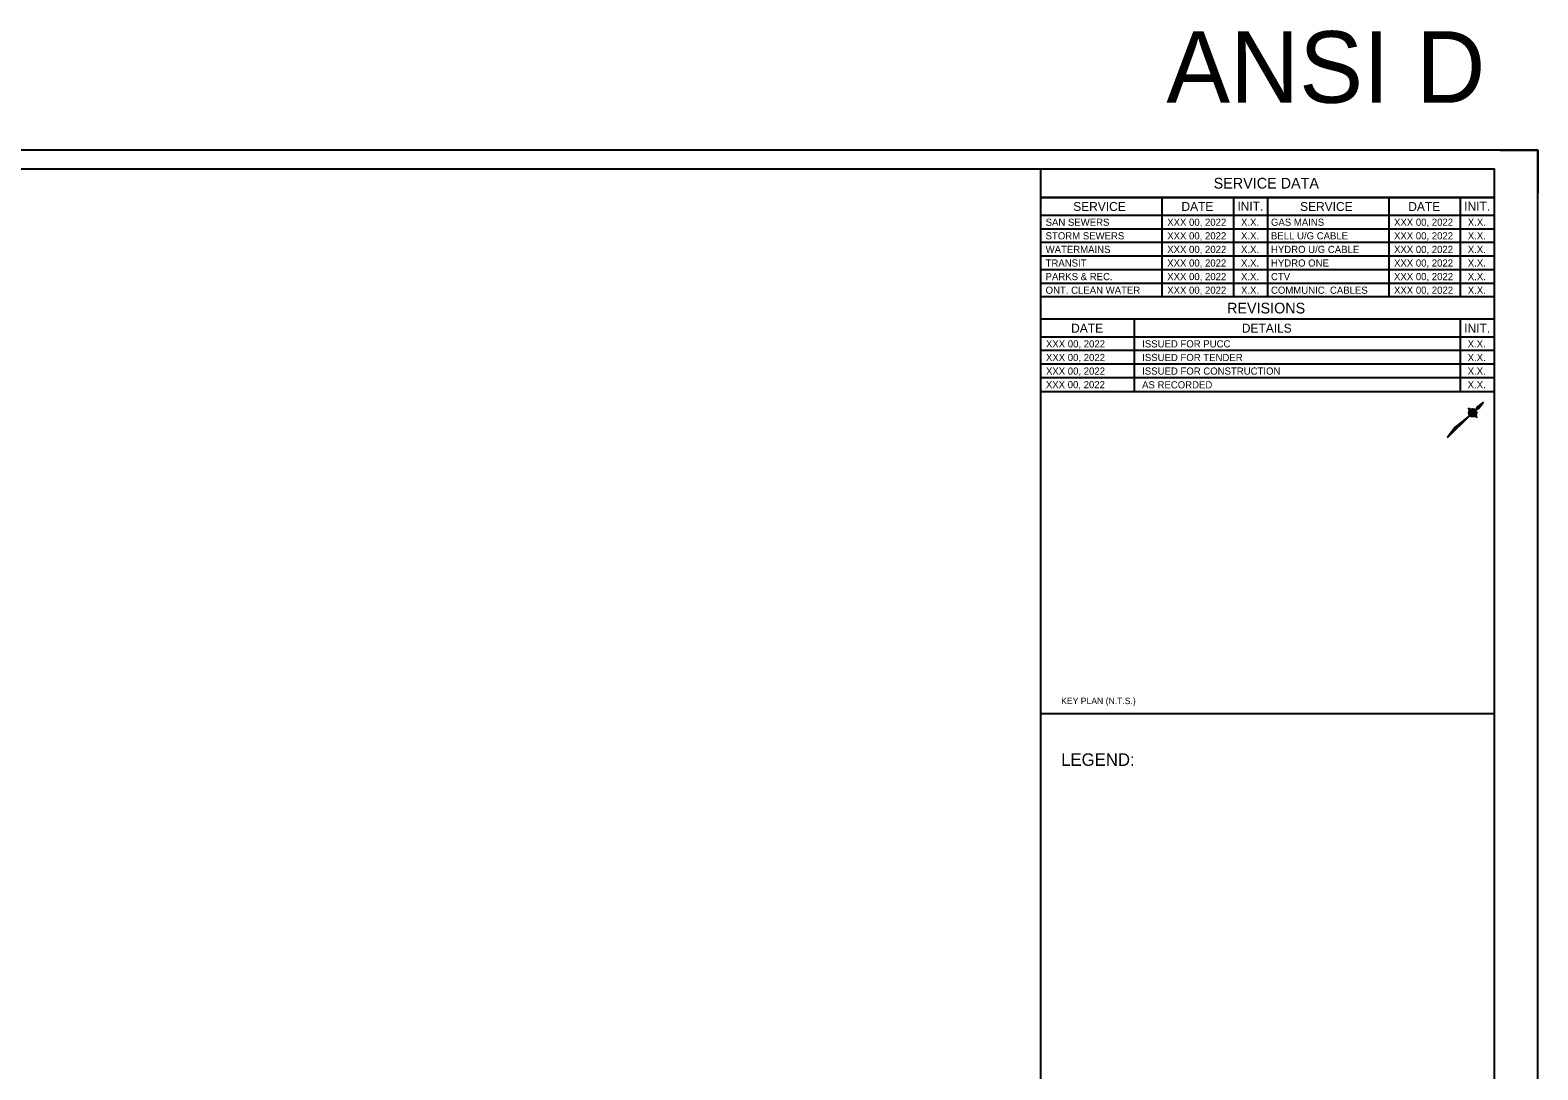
# Model space of a CAD drawing. Extents: x 613360 to 613780, y 4825621 to 4825911.
# Drawn here: x 613569.5 to 613780.3, y 4825766.2 to 4825911.5 of the extents above; entities that cross this region are included whole.
import ezdxf

# ---------------------------------------------------------------- set-up
doc = ezdxf.new("R2010")
doc.units = 0
for name, color, linetype in [('G-ANNO-KEYP', 7, 'Continuous'), ('G-ANNO-LEGN', 7, 'Continuous'), ('G-ANNO-NPLT', 7, 'Continuous'), ('G-ANNO-TTLB-TEXT', 7, 'Continuous'), ('G-TTLB-OTLN', 7, 'Continuous'), ('G-TTLB-OTLN-PB', 7, 'Continuous')]:
    doc.layers.add(name, color=color, linetype=linetype)

msp = doc.modelspace()

# ---------------------------------------------------------------- linework, layer by layer
at = {"layer": 'G-ANNO-KEYP'}
for p, q in [((613770.76, 4825857.62), (613767.64, 4825854.56)), ((613767.74, 4825854.69), (613770.74, 4825857.6)), ((613770.76, 4825857.62), (613768.73, 4825855.97)), ((613770.77, 4825858.38), (613770.51, 4825858.64)), ((613770.56, 4825858.46), (613770.71, 4825858.31)), ((613770.68, 4825858.07), (613770.78, 4825858.17)), ((613770.68, 4825858.05), (613770.76, 4825858.13)), ((613770.68, 4825858.03), (613770.76, 4825858.11)), ((613770.68, 4825858.01), (613770.75, 4825858.08)), ((613770.68, 4825857.99), (613770.74, 4825858.06)), ((613770.68, 4825857.97), (613770.74, 4825858.04)), ((613770.68, 4825857.96), (613770.74, 4825858.02)), ((613770.68, 4825857.94), (613770.74, 4825858)), ((613770.68, 4825857.92), (613770.74, 4825857.98)), ((613770.68, 4825857.91), (613770.74, 4825857.96)), ((613770.69, 4825858.59), (613770.84, 4825858.44)), ((613770.69, 4825858.12), (613770.85, 4825858.28)), ((613770.69, 4825858.1), (613770.8, 4825858.2)), ((613770.69, 4825857.89), (613770.74, 4825857.94)), ((613770.69, 4825857.87), (613770.75, 4825857.93)), ((613770.7, 4825858.15), (613771.01, 4825858.44)), ((613770.7, 4825857.86), (613770.75, 4825857.91)), ((613770.7, 4825857.85), (613770.75, 4825857.9)), ((613770.71, 4825858.18), (613770.97, 4825858.43)), ((613770.71, 4825857.83), (613770.76, 4825857.88)), ((613770.71, 4825857.82), (613770.76, 4825857.87)), ((613770.72, 4825857.8), (613770.77, 4825857.85)), ((613770.72, 4825857.79), (613770.77, 4825857.84)), ((613770.73, 4825858.21), (613770.94, 4825858.42)), ((613770.73, 4825857.78), (613770.78, 4825857.82)), ((613770.74, 4825857.77), (613770.78, 4825857.81)), ((613770.74, 4825857.75), (613770.79, 4825857.8)), ((613770.75, 4825857.74), (613770.8, 4825857.79)), ((613770.76, 4825858.26), (613770.89, 4825858.39)), ((613770.76, 4825857.73), (613770.8, 4825857.78)), ((613770.77, 4825857.72), (613770.81, 4825857.76)), ((613770.77, 4825857.71), (613770.82, 4825857.75)), ((613770.78, 4825857.7), (613770.83, 4825857.74)), ((613770.79, 4825857.69), (613770.84, 4825857.73)), ((613770.8, 4825857.68), (613770.85, 4825857.72)), ((613770.81, 4825857.67), (613770.86, 4825857.71)), ((613770.82, 4825857.66), (613770.86, 4825857.7)), ((613770.83, 4825857.65), (613770.87, 4825857.69)), ((613770.84, 4825857.64), (613770.88, 4825857.68)), ((613770.85, 4825857.63), (613770.9, 4825857.67)), ((613770.86, 4825857.62), (613770.91, 4825857.67)), ((613770.87, 4825858.3), (613771.03, 4825858.45)), ((613770.87, 4825858.3), (613771.03, 4825858.45)), ((613770.87, 4825857.61), (613770.92, 4825857.66)), ((613770.88, 4825857.61), (613770.93, 4825857.65)), ((613771.16, 4825858.25), (613770.89, 4825857.99)), ((613770.89, 4825857.99), (613770.92, 4825857.96)), ((613770.89, 4825857.6), (613770.94, 4825857.64)), ((613770.91, 4825857.59), (613770.95, 4825857.64)), ((613770.92, 4825857.96), (613771.11, 4825858.14)), ((613770.92, 4825857.58), (613770.97, 4825857.63)), ((613770.93, 4825857.58), (613770.98, 4825857.62)), ((613770.94, 4825857.57), (613770.99, 4825857.62)), ((613770.95, 4825858.35), (613771.06, 4825858.46)), ((613770.96, 4825857.56), (613771.01, 4825857.61)), ((613770.97, 4825857.56), (613771.02, 4825857.61)), ((613770.98, 4825857.55), (613771.04, 4825857.6)), ((613770.99, 4825858.37), (613771.08, 4825858.46)), ((613771, 4825857.55), (613771.05, 4825857.6)), ((613771.01, 4825857.54), (613771.07, 4825857.6)), ((613771.02, 4825858.38), (613771.1, 4825858.46)), ((613771.03, 4825857.54), (613771.08, 4825857.59)), ((613771.04, 4825857.54), (613771.1, 4825857.59)), ((613771.05, 4825858.39), (613771.12, 4825858.46)), ((613771.06, 4825857.53), (613771.12, 4825857.59)), ((613771.07, 4825858.39), (613771.14, 4825858.47)), ((613771.08, 4825857.53), (613771.14, 4825857.59)), ((613771.09, 4825857.53), (613771.16, 4825857.59)), ((613771.1, 4825858.4), (613771.16, 4825858.46)), ((613771.11, 4825858.14), (613771.12, 4825857.75)), ((613771.11, 4825857.53), (613771.18, 4825857.59)), ((613771.12, 4825858.4), (613771.18, 4825858.46)), ((613771.12, 4825857.75), (613771.39, 4825858.02)), ((613771.13, 4825857.53), (613771.2, 4825857.59)), ((613771.14, 4825858.4), (613771.2, 4825858.46)), ((613771.15, 4825857.52), (613771.22, 4825857.6)), ((613771.16, 4825858.4), (613771.22, 4825858.46)), ((613771.17, 4825857.87), (613771.16, 4825858.25)), ((613771.36, 4825858.05), (613771.17, 4825857.87)), ((613771.17, 4825857.53), (613771.25, 4825857.6)), ((613771.18, 4825858.4), (613771.23, 4825858.46)), ((613771.19, 4825858.4), (613771.25, 4825858.45)), ((613771.19, 4825857.53), (613771.28, 4825857.61)), ((613771.21, 4825858.4), (613771.27, 4825858.45)), ((613771.21, 4825857.53), (613771.31, 4825857.62)), ((613771.23, 4825858.39), (613771.28, 4825858.45)), ((613771.24, 4825858.39), (613771.3, 4825858.44)), ((613771.24, 4825857.53), (613771.35, 4825857.64)), ((613771.26, 4825858.39), (613771.31, 4825858.44)), ((613771.26, 4825857.54), (613771.6, 4825857.86)), ((613771.27, 4825858.38), (613771.32, 4825858.43)), ((613771.29, 4825858.38), (613771.34, 4825858.42)), ((613771.29, 4825857.55), (613771.59, 4825857.84)), ((613771.3, 4825858.37), (613771.35, 4825858.42)), ((613771.31, 4825858.37), (613771.36, 4825858.41)), ((613771.32, 4825857.56), (613771.58, 4825857.81)), ((613771.32, 4825857.56), (613771.58, 4825857.81)), ((613771.33, 4825858.36), (613771.38, 4825858.41)), ((613771.34, 4825858.35), (613771.39, 4825858.4)), ((613771.35, 4825858.35), (613771.4, 4825858.39)), ((613771.36, 4825858.34), (613771.41, 4825858.38)), ((613771.39, 4825858.02), (613771.36, 4825858.05)), ((613771.36, 4825857.58), (613771.56, 4825857.77)), ((613771.38, 4825858.33), (613771.42, 4825858.38)), ((613771.39, 4825858.32), (613771.43, 4825858.37)), ((613771.4, 4825858.31), (613771.44, 4825858.36)), ((613771.41, 4825858.31), (613771.45, 4825858.35)), ((613771.41, 4825857.6), (613771.53, 4825857.72)), ((613771.42, 4825858.3), (613771.46, 4825858.34)), ((613771.43, 4825858.29), (613771.47, 4825858.33)), ((613771.44, 4825858.28), (613771.48, 4825858.32)), ((613771.45, 4825858.27), (613771.49, 4825858.31)), ((613771.6, 4825857.4), (613771.45, 4825857.55)), ((613771.46, 4825858.26), (613771.5, 4825858.3)), ((613771.47, 4825858.25), (613771.51, 4825858.29)), ((613771.47, 4825858.24), (613771.52, 4825858.28)), ((613771.48, 4825858.22), (613771.53, 4825858.27)), ((613771.49, 4825858.21), (613771.54, 4825858.26)), ((613771.49, 4825857.78), (613771.6, 4825857.89)), ((613771.5, 4825858.2), (613771.54, 4825858.25)), ((613771.5, 4825858.19), (613771.55, 4825858.23)), ((613771.51, 4825858.18), (613771.56, 4825858.22)), ((613771.51, 4825857.82), (613771.61, 4825857.91)), ((613771.52, 4825858.16), (613771.56, 4825858.21)), ((613771.52, 4825858.15), (613771.57, 4825858.2)), ((613771.53, 4825858.14), (613771.58, 4825858.18)), ((613771.53, 4825858.12), (613771.58, 4825858.17)), ((613771.53, 4825857.85), (613771.61, 4825857.94)), ((613771.53, 4825857.61), (613771.78, 4825857.35)), ((613771.54, 4825858.11), (613771.59, 4825858.16)), ((613771.54, 4825858.09), (613771.59, 4825858.14)), ((613771.54, 4825858.08), (613771.6, 4825858.13)), ((613771.54, 4825857.91), (613771.62, 4825857.98)), ((613771.54, 4825857.88), (613771.61, 4825857.96)), ((613771.55, 4825858.06), (613771.6, 4825858.11)), ((613771.55, 4825858.05), (613771.6, 4825858.1)), ((613771.55, 4825858.03), (613771.61, 4825858.08)), ((613771.55, 4825858.01), (613771.61, 4825858.07)), ((613771.55, 4825857.99), (613771.61, 4825858.05)), ((613771.55, 4825857.97), (613771.61, 4825858.03)), ((613771.55, 4825857.95), (613771.62, 4825858.01)), ((613771.55, 4825857.93), (613771.62, 4825858)), ((613771.74, 4825857.53), (613771.59, 4825857.68)), ((613772.61, 4825859.43), (613771.63, 4825858.47)), ((613771.8, 4825858.85), (613771.63, 4825858.47)), ((613772.01, 4825858.63), (613771.63, 4825858.47)), ((613771.64, 4825858.47), (613772.57, 4825859.38)), ((613771.67, 4825858.49), (613772.52, 4825859.31)), ((613771.71, 4825858.5), (613772.47, 4825859.24)), ((613771.74, 4825858.51), (613772.42, 4825859.17)), ((613771.78, 4825858.53), (613772.37, 4825859.1)), ((613772.61, 4825859.43), (613771.8, 4825858.85)), ((613771.81, 4825858.54), (613772.32, 4825859.04)), ((613771.84, 4825858.56), (613772.27, 4825858.97)), ((613771.88, 4825858.57), (613772.22, 4825858.9)), ((613771.91, 4825858.59), (613772.16, 4825858.83)), ((613771.95, 4825858.6), (613772.11, 4825858.76)), ((613771.98, 4825858.61), (613772.06, 4825858.69)), ((613772.61, 4825859.43), (613772.01, 4825858.63)), ((613768.73, 4825855.97), (613767.64, 4825854.56)), ((613767.68, 4825854.61), (613769.09, 4825855.98)), ((613767.8, 4825854.77), (613770.62, 4825857.51)), ((613767.86, 4825854.84), (613770.5, 4825857.41)), ((613767.92, 4825854.92), (613770.39, 4825857.31)), ((613767.98, 4825854.99), (613770.27, 4825857.22)), ((613768.04, 4825855.07), (613770.15, 4825857.12)), ((613768.1, 4825855.15), (613770.03, 4825857.02)), ((613768.15, 4825855.22), (613769.91, 4825856.92)), ((613768.21, 4825855.3), (613769.79, 4825856.83)), ((613768.27, 4825855.37), (613769.67, 4825856.73)), ((613768.33, 4825855.45), (613769.55, 4825856.63)), ((613768.39, 4825855.53), (613769.43, 4825856.54)), ((613768.45, 4825855.6), (613769.31, 4825856.44)), ((613768.51, 4825855.68), (613769.19, 4825856.34)), ((613768.57, 4825855.75), (613769.07, 4825856.25)), ((613768.62, 4825855.83), (613768.95, 4825856.15)), ((613768.68, 4825855.91), (613768.83, 4825856.05))]:
    msp.add_line(p, q, dxfattribs=at)
for points in [[(613767.64, 4825854.56), (613770.76, 4825857.62), (613768.73, 4825855.97)], [(613771.63, 4825858.47), (613772.01, 4825858.63), (613772.61, 4825859.43)]]:
    msp.add_lwpolyline(points, close=True, dxfattribs=at)
for radius in [0.541, 0.47, 0.407, 0.348]:
    msp.add_circle((613771.15, 4825858), radius, dxfattribs=at)
at = {"layer": 'G-TTLB-OTLN'}
for p, q in [((613710.78, 4825860.98), (613710.78, 4825892.08)), ((613774.18, 4825888.08), (613710.78, 4825888.08)), ((613710.78, 4825888.08), (613774.18, 4825888.08)), ((613727.73, 4825888.08), (613727.73, 4825874.18)), ((613737.73, 4825888.08), (613737.73, 4825874.18)), ((613742.48, 4825888.08), (613742.48, 4825874.18)), ((613759.43, 4825888.08), (613759.43, 4825874.18)), ((613769.43, 4825888.08), (613769.43, 4825874.18)), ((613774.18, 4825885.58), (613710.78, 4825885.58)), ((613774.18, 4825883.68), (613710.78, 4825883.68)), ((613774.18, 4825881.78), (613710.78, 4825881.78)), ((613774.18, 4825879.88), (613710.78, 4825879.88)), ((613774.18, 4825877.98), (613710.78, 4825877.98)), ((613774.18, 4825876.08), (613710.78, 4825876.08)), ((613774.18, 4825874.18), (613710.78, 4825874.18)), ((613774.18, 4825871.08), (613710.78, 4825871.08)), ((613723.83, 4825871.08), (613723.83, 4825860.98)), ((613769.43, 4825871.08), (613769.43, 4825860.98)), ((613774.18, 4825868.58), (613710.78, 4825868.58)), ((613774.18, 4825866.68), (613710.78, 4825866.68)), ((613774.18, 4825864.78), (613710.78, 4825864.78)), ((613774.18, 4825862.88), (613710.78, 4825862.88)), ((613710.78, 4825623.51), (613710.78, 4825815.93))]:
    msp.add_line(p, q, dxfattribs=at)
for points in [[(613380.09, 4825892.08), (613774.18, 4825892.08), (613774.18, 4825623.51), (613380.09, 4825623.51)], [(613710.78, 4825860.98), (613774.18, 4825860.98), (613774.18, 4825815.93), (613710.78, 4825815.93)]]:
    msp.add_lwpolyline(points, close=True, dxfattribs=at)
at = {"layer": 'G-TTLB-OTLN-PB'}
for p, q in [((613774.98, 4825894.68), (613780.27, 4825894.68)), ((613780.27, 4825894.68), (613780.27, 4825888.68))]:
    msp.add_line(p, q, dxfattribs=at)
msp.add_lwpolyline([(613359.58, 4825620.91), (613780.27, 4825620.91), (613780.27, 4825894.68), (613359.58, 4825894.68)], close=True, dxfattribs=at)

# ---------------------------------------------------------------- texts
at = {"layer": 'G-ANNO-KEYP'}
msp.add_text('KEY PLAN (N.T.S.)', height=0.9, rotation=359.9998, dxfattribs=at).set_placement((613713.64, 4825817.29))
at = {"layer": 'G-ANNO-LEGN'}
msp.add_text('LEGEND:', height=1.75, rotation=360, dxfattribs=at).set_placement((613713.64, 4825808.66))
at = {"layer": 'G-ANNO-NPLT'}
msp.add_text('ANSI D', height=10, dxfattribs=at).set_placement((613728.34, 4825901.32))
at = {"layer": 'G-ANNO-TTLB-TEXT'}
for s, height, p in [('SERVICE DATA', 1.5, (613734.96, 4825889.33)), ('SERVICE', 1.25, (613715.33, 4825886.2)), ('DATE', 1.25, (613730.46, 4825886.21)), ('INIT.', 1.25, (613738.28, 4825886.24)), ('SERVICE', 1.25, (613747.04, 4825886.2)), ('DATE', 1.25, (613762.16, 4825886.2)), ('INIT.', 1.25, (613769.98, 4825886.24)), ('SAN SEWERS', 1, (613711.47, 4825884.13)), ('GAS MAINS', 1, (613742.97, 4825884.13)), ('STORM SEWERS', 1, (613711.47, 4825882.23)), ('BELL U/G CABLE', 1, (613742.97, 4825882.23)), ('WATERMAINS', 1, (613711.47, 4825880.33)), ('HYDRO U/G CABLE', 1, (613742.97, 4825880.33)), ('TRANSIT', 1, (613711.47, 4825878.43)), ('HYDRO ONE', 1, (613742.97, 4825878.43)), ('PARKS & REC.', 1, (613711.47, 4825876.53)), ('CTV', 1, (613742.97, 4825876.53)), ('ONT. CLEAN WATER ', 1, (613711.47, 4825874.63)), ('COMMUNIC. CABLES', 1, (613742.97, 4825874.63)), ('REVISIONS', 1.5, (613736.83, 4825871.88)), ('DATE', 1.25, (613715.04, 4825869.2)), ('DETAILS', 1.25, (613738.9, 4825869.2)), ('INIT.', 1.25, (613769.98, 4825869.2)), ('XXX 00, 2022', 1, (613711.52, 4825863.33)), ('XXX 00, 2022', 1, (613711.51, 4825861.43))]:
    msp.add_text(s, height=height, dxfattribs=at).set_placement(p)
for s, p in [('XXX 00, 2022', (613728.47, 4825884.13)), ('X.X.', (613738.78, 4825884.13)), ('XXX 00, 2022', (613760.17, 4825884.13)), ('X.X.', (613770.48, 4825884.13)), ('XXX 00, 2022', (613728.47, 4825882.23)), ('X.X.', (613738.78, 4825882.23)), ('XXX 00, 2022', (613760.17, 4825882.23)), ('X.X.', (613770.48, 4825882.23)), ('XXX 00, 2022', (613728.47, 4825880.33)), ('X.X.', (613738.78, 4825880.33)), ('XXX 00, 2022', (613760.17, 4825880.33)), ('X.X.', (613770.48, 4825880.33)), ('XXX 00, 2022', (613728.47, 4825878.43)), ('X.X.', (613738.78, 4825878.43)), ('XXX 00, 2022', (613760.17, 4825878.43)), ('X.X.', (613770.48, 4825878.43)), ('XXX 00, 2022', (613728.47, 4825876.53)), ('X.X.', (613738.78, 4825876.53)), ('XXX 00, 2022', (613760.17, 4825876.53)), ('X.X.', (613770.48, 4825876.53)), ('XXX 00, 2022', (613728.47, 4825874.63)), ('X.X.', (613738.78, 4825874.63)), ('XXX 00, 2022', (613760.17, 4825874.63)), ('X.X.', (613770.48, 4825874.63)), ('XXX 00, 2022', (613711.52, 4825867.13)), ('ISSUED FOR PUCC', (613724.97, 4825867.13)), ('X.X.', (613770.46, 4825867.13)), ('XXX 00, 2022', (613711.52, 4825865.23)), ('ISSUED FOR TENDER', (613724.97, 4825865.23)), ('X.X.', (613770.46, 4825865.23)), ('ISSUED FOR CONSTRUCTION', (613724.97, 4825863.33)), ('X.X.', (613770.46, 4825863.33)), ('AS RECORDED', (613724.96, 4825861.41)), ('X.X.', (613770.46, 4825861.43))]:
    msp.add_text(s, height=1, rotation=360, dxfattribs=at).set_placement(p)

doc.saveas('drawing.dxf')
